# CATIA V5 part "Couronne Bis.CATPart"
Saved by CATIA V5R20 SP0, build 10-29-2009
Part number: Couronne Bis
Bounding box of the stored display mesh (mm): x -23.493 to 23.493, y -23.493 to 23.493, z -1.5 to 1.5
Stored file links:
  G:\Khaled_CFAO_2011\SIL\SIL_GR1\blaboucarri\Khaled\CAD_CATIA\Couronne Bis.CATPart
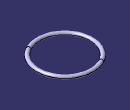
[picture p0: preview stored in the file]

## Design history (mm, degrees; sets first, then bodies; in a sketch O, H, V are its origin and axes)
Parameters
  `rayon section` = 1.5 mm
  `rayon couronne` = 22 mm
Body1 (main body)
  Sketch1 on xy-plane, origin (0, 0, 0), H (1, 0, 0), V (0, 1, 0)
    circle A1 centre (0, 0) radius 22
    radius A1 = 22 {= `rayon couronne`}
  Sketch2 on yz-plane, origin (0, 0, 0), H (0, 1, 0), V (0, 0, 1)
    circle A1 centre (-22, 0) radius 1.5
    point P1 (-22, 0)
    radius A1 = 1.5 {= `rayon section`}
    coincidence: P1 H
  Shaft1: profile Sketch2, axis Sketch2.V, angle 360
  Point1: type OnCurve, Support Sketch1, RefPoint {extremum Reference Sketch1, Direction (1, 2, 3)}, Length 1.6
  DatumCurve1
  Line1: type PtDir, RefPoint Point1, Direction DatumCurve1, Start -2, End 2
  Plane1: type Normal, Curve Line1, RefPoint Point1
  Line2: type Normal, RefPoint Sketch1.O, RefSkin xy-plane, Start -2, End 2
